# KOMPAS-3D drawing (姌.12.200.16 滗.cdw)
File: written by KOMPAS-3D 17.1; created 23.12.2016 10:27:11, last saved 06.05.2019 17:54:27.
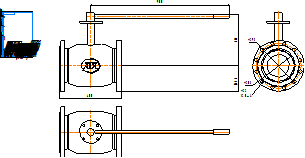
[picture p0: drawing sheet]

Sheet 1: A4, portrait

Title block, sheet 1: name: КШ.12.200.16 фф; material: Внимание! Данный продукт является объектом авторского права ООО «Торговый Дом АДЛ». / Запрещается изменение, копирование, распространение / (в том числе путем копирования на другие сайты и ресурсы в Интернете) / или любое иное использование информации и объектов без предварительного / согласия правообладателя (ООО «Торговый Дом АДЛ»).; sheets: 1; organisation: ООО "Торговый дом АДЛ"; sheet format: A4; stored path: C:\Users\tra\Desktop\2д чертежи\Шаровые краны БИВАЛ\КШ_Бивал_серия_11_12\KOMPAS_2D\КШ.12.200.16 фф.cdw

Views: Вид 1, Проекционный вид 2, Проекционный вид 3
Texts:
  Klimkovich
  ADL
Dimensions and other numbers on the sheet: 400; 900; 336; 167,5; 295; 203; 22; 12 Отв.; 1:1; 1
